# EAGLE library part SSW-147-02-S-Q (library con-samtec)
THROUGH-HOLE .025" SQ POST SOCKET Source: Samtec SSW.pdf
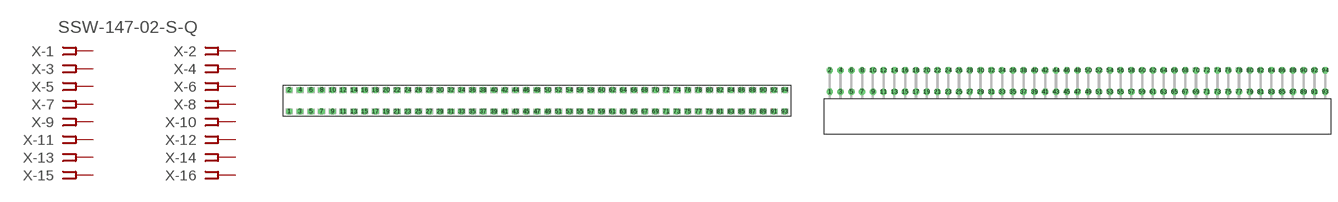
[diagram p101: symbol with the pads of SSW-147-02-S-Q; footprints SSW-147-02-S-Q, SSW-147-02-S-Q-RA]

Designator prefix X; gates -1=FPINV -2=FPIN -3=FPIN -4=FPIN -5=FPIN -6=FPIN -7=FPIN -8=FPIN -9=FPIN -10=FPIN -11=FPIN -12=FPIN -13=FPIN -14=FPIN -15=FPIN -16=FPIN -17=FPIN -18=FPIN -19=FPIN -20=FPIN -21=FPIN -22=FPIN -23=FPIN -24=FPIN -25=FPIN -26=FPIN -27=FPIN -28=FPIN -29=FPIN -30=FPIN -31=FPIN -32=FPIN -33=FPIN -34=FPIN -35=FPIN -36=FPIN -37=FPIN -38=FPIN -39=FPIN -40=FPIN -41=FPIN -42=FPIN -43=FPIN -44=FPIN -45=FPIN -46=FPIN -47=FPIN -48=FPIN -49=FPIN -50=FPIN -51=FPIN -52=FPIN -53=FPIN -54=FPIN -55=FPIN -56=FPIN -57=FPIN -58=FPIN -59=FPIN -60=FPIN -61=FPIN -62=FPIN -63=FPIN -64=FPIN -65=FPIN -66=FPIN -67=FPIN -68=FPIN -69=FPIN -70=FPIN -71=FPIN -72=FPIN -73=FPIN -74=FPIN -75=FPIN -76=FPIN -77=FPIN -78=FPIN -79=FPIN -80=FPIN -81=FPIN -82=FPIN -83=FPIN -84=FPIN -85=FPIN -86=FPIN -87=FPIN -88=FPIN -89=FPIN -90=FPIN -91=FPIN -92=FPIN -93=FPIN -94=FPIN

## SSW-147-02-S-Q (OC_FARNELL: unknown; OC_NEWARK: unknown)  [SSW-147-02-S-Q]
1  -1:1  pas
2  -2:1  pas
3  -3:1  pas
4  -4:1  pas
5  -5:1  pas
6  -6:1  pas
7  -7:1  pas
8  -8:1  pas
9  -9:1  pas
10  -10:1  pas
11  -11:1  pas
12  -12:1  pas
13  -13:1  pas
14  -14:1  pas
15  -15:1  pas
16  -16:1  pas
17  -17:1  pas
18  -18:1  pas
19  -19:1  pas
20  -20:1  pas
21  -21:1  pas
22  -22:1  pas
23  -23:1  pas
24  -24:1  pas
25  -25:1  pas
26  -26:1  pas
27  -27:1  pas
28  -28:1  pas
29  -29:1  pas
30  -30:1  pas
31  -31:1  pas
32  -32:1  pas
33  -33:1  pas
34  -34:1  pas
35  -35:1  pas
36  -36:1  pas
37  -37:1  pas
38  -38:1  pas
39  -39:1  pas
40  -40:1  pas
41  -41:1  pas
42  -42:1  pas
43  -43:1  pas
44  -44:1  pas
45  -45:1  pas
46  -46:1  pas
47  -47:1  pas
48  -48:1  pas
49  -49:1  pas
50  -50:1  pas
51  -51:1  pas
52  -52:1  pas
53  -53:1  pas
54  -54:1  pas
55  -55:1  pas
56  -56:1  pas
57  -57:1  pas
58  -58:1  pas
59  -59:1  pas
60  -60:1  pas
61  -61:1  pas
62  -62:1  pas
63  -63:1  pas
64  -64:1  pas
65  -65:1  pas
66  -66:1  pas
67  -67:1  pas
68  -68:1  pas
69  -69:1  pas
70  -70:1  pas
71  -71:1  pas
72  -72:1  pas
73  -73:1  pas
74  -74:1  pas
75  -75:1  pas
76  -76:1  pas
77  -77:1  pas
78  -78:1  pas
79  -79:1  pas
80  -80:1  pas
81  -81:1  pas
82  -82:1  pas
83  -83:1  pas
84  -84:1  pas
85  -85:1  pas
86  -86:1  pas
87  -87:1  pas
88  -88:1  pas
89  -89:1  pas
90  -90:1  pas
91  -91:1  pas
92  -92:1  pas
93  -93:1  pas
94  -94:1  pas

## SSW-147-02-S-QRA (OC_FARNELL: unknown; OC_NEWARK: unknown)  [SSW-147-02-S-Q-RA]
Pads as for SSW-147-02-S-Q

## Footprint SSW-147-02-S-Q (pad centres in mm)
THROUGH-HOLE .025" SQ POST SOCKET Source: Samtec SSW.pdf
drill 1 pad 1.5 octagon: 1 -58.42,-2.54; 2 -58.42,2.54; 3 -55.88,-2.54; 4 -55.88,2.54; 5 -53.34,-2.54; 6 -53.34,2.54; 7 -50.8,-2.54; 8 -50.8,2.54; 9 -48.26,-2.54; 10 -48.26,2.54; 11 -45.72,-2.54; 12 -45.72,2.54; 13 -43.18,-2.54; 14 -43.18,2.54; 15 -40.64,-2.54; 16 -40.64,2.54; 17 -38.1,-2.54; 18 -38.1,2.54; 19 -35.56,-2.54; 20 -35.56,2.54; 21 -33.02,-2.54; 22 -33.02,2.54; 23 -30.48,-2.54; 24 -30.48,2.54; 25 -27.94,-2.54; 26 -27.94,2.54; 27 -25.4,-2.54; 28 -25.4,2.54; 29 -22.86,-2.54; 30 -22.86,2.54; 31 -20.32,-2.54; 32 -20.32,2.54; 33 -17.78,-2.54; 34 -17.78,2.54; 35 -15.24,-2.54; 36 -15.24,2.54; 37 -12.7,-2.54; 38 -12.7,2.54; 39 -10.16,-2.54; 40 -10.16,2.54; 41 -7.62,-2.54; 42 -7.62,2.54; 43 -5.08,-2.54; 44 -5.08,2.54; 45 -2.54,-2.54; 46 -2.54,2.54; 47 0,-2.54; 48 0,2.54; 49 2.54,-2.54; 50 2.54,2.54; 51 5.08,-2.54; 52 5.08,2.54; 53 7.62,-2.54; 54 7.62,2.54; 55 10.16,-2.54; 56 10.16,2.54; 57 12.7,-2.54; 58 12.7,2.54; 59 15.24,-2.54; 60 15.24,2.54; 61 17.78,-2.54; 62 17.78,2.54; 63 20.32,-2.54; 64 20.32,2.54; 65 22.86,-2.54; 66 22.86,2.54; 67 25.4,-2.54; 68 25.4,2.54; 69 27.94,-2.54; 70 27.94,2.54; 71 30.48,-2.54; 72 30.48,2.54; 73 33.02,-2.54; 74 33.02,2.54; 75 35.56,-2.54; 76 35.56,2.54; 77 38.1,-2.54; 78 38.1,2.54; 79 40.64,-2.54; 80 40.64,2.54; 81 43.18,-2.54; 82 43.18,2.54; 83 45.72,-2.54; 84 45.72,2.54; 85 48.26,-2.54; 86 48.26,2.54; 87 50.8,-2.54; 88 50.8,2.54; 89 53.34,-2.54; 90 53.34,2.54; 91 55.88,-2.54; 92 55.88,2.54; 93 58.42,-2.54; 94 58.42,2.54

## Footprint SSW-147-02-S-Q-RA (pad centres in mm)
THROUGH-HOLE .025" SQ POST SOCKET Source: Samtec SSW.pdf
drill 1 pad 1.5 octagon: 1 -58.42,1.524; 2 -58.42,6.604; 3 -55.88,1.524; 4 -55.88,6.604; 5 -53.34,1.524; 6 -53.34,6.604; 7 -50.8,1.524; 8 -50.8,6.604; 9 -48.26,1.524; 10 -48.26,6.604; 11 -45.72,1.524; 12 -45.72,6.604; 13 -43.18,1.524; 14 -43.18,6.604; 15 -40.64,1.524; 16 -40.64,6.604; 17 -38.1,1.524; 18 -38.1,6.604; 19 -35.56,1.524; 20 -35.56,6.604; 21 -33.02,1.524; 22 -33.02,6.604; 23 -30.48,1.524; 24 -30.48,6.604; 25 -27.94,1.524; 26 -27.94,6.604; 27 -25.4,1.524; 28 -25.4,6.604; 29 -22.86,1.524; 30 -22.86,6.604; 31 -20.32,1.524; 32 -20.32,6.604; 33 -17.78,1.524; 34 -17.78,6.604; 35 -15.24,1.524; 36 -15.24,6.604; 37 -12.7,1.524; 38 -12.7,6.604; 39 -10.16,1.524; 40 -10.16,6.604; 41 -7.62,1.524; 42 -7.62,6.604; 43 -5.08,1.524; 44 -5.08,6.604; 45 -2.54,1.524; 46 -2.54,6.604; 47 0,1.524; 48 0,6.604; 49 2.54,1.524; 50 2.54,6.604; 51 5.08,1.524; 52 5.08,6.604; 53 7.62,1.524; 54 7.62,6.604; 55 10.16,1.524; 56 10.16,6.604; 57 12.7,1.524; 58 12.7,6.604; 59 15.24,1.524; 60 15.24,6.604; 61 17.78,1.524; 62 17.78,6.604; 63 20.32,1.524; 64 20.32,6.604; 65 22.86,1.524; 66 22.86,6.604; 67 25.4,1.524; 68 25.4,6.604; 69 27.94,1.524; 70 27.94,6.604; 71 30.48,1.524; 72 30.48,6.604; 73 33.02,1.524; 74 33.02,6.604; 75 35.56,1.524; 76 35.56,6.604; 77 38.1,1.524; 78 38.1,6.604; 79 40.64,1.524; 80 40.64,6.604; 81 43.18,1.524; 82 43.18,6.604; 83 45.72,1.524; 84 45.72,6.604; 85 48.26,1.524; 86 48.26,6.604; 87 50.8,1.524; 88 50.8,6.604; 89 53.34,1.524; 90 53.34,6.604; 91 55.88,1.524; 92 55.88,6.604; 93 58.42,1.524; 94 58.42,6.604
